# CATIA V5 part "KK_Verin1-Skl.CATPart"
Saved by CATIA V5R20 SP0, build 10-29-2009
Part number: Verin1-Skl
Bounding box of the stored display mesh (mm): x -50.294 to -20, y 61.535 to 86.432, z 0 to 100
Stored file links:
  G:\Khaled_CFAO_2011\ST2M\ST2M_GR1\msallin\Khaled\Version_Finale\KK_Verin1-Skl.CATPart
  C:\Users\Mathieu\Desktop\Think Motion\JOUG-MELEE2.CATProduct
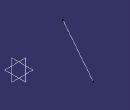
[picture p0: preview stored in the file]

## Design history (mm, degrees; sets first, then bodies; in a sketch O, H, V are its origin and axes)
Set1
  Point1 to Point12: linked copy from another document
Set2
  Line1: type PtPt, FirstPoint Point1, SecondPoint Point2
Body1 (main body)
